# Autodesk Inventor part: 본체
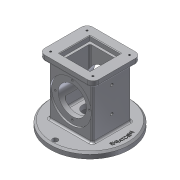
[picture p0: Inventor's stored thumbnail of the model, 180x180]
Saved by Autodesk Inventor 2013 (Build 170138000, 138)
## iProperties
Created: 2019-08
Part Number: 본체
Material: 알루미늄 6061
Document SubType Name: Modeling
Designer: Administrator
Density: 2.71 g/cm^3
Mass: 1042.69 g
Surface Area: 783.577 cm^2
Volume: 384.757 cm^3
Author: Administrator
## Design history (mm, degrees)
sketch "스케치1"
  geometry: L1 (33, 37)-(-33, 37); L2 (-33, 37)-(-33, -37); L3 (-33, -37)-(33, -37); L4 (33, -37)-(33, 37); L5 (33, 37)-(-33, -37); L6 (-33, 37)-(33, -37); 1 further point
  constraints: 12 end point, 2 midpoint, 2 parallel, 1 horizontal, 1 perpendicular
  dimensions: "d0" = 74 distance of L1.end L2.end; "d2" = 66 distance of L1.start L1.end
extrude "돌출1" new body sketch "스케치1" stored distance "d3" = 108; taper "d4" = 0 deg
sketch "스케치2"
  geometry: 2 further points
  constraints: 1 coincident
hole "구멍1" sketch "스케치2" at (54, 37) diameter "d5" = 48; stored, may be unused: countersink angle "d9" = 90 deg, drill point angle "d11" = 118 deg; dims "d6" = 6, "d7" = 70, "d8" = 3, "d10" = 48
sketch "스케치3"
  geometry: C1 r 35 at (0, 0) reference; 1 further point
  constraints: 1 horizontal alignment
  dimensions: "d12" = 29 distance of C1.centre point (-29, 0)
hole "구멍2" sketch "스케치3" at (-29, 0) diameter "d13" = 3.242; stored, may be unused: countersink angle "d17" = 90 deg, drill point angle "d19" = 118 deg; dims "d14" = 4, "d15" = 70, "d16" = 3, "d18" = 6
sketch "스케치4"
  geometry: C1 r 67.5 at (0, 0); 1 further point
  constraints: 1 centre point, 1 coincident
  dimensions: "d23" = 135 diameter of C1
extrude "돌출2" join sketch "스케치4" distance "d25" = 10; taper "d26" = 0 deg
sketch "스케치5"
  geometry: L1 (41, 46)-(-41, 46); L2 (-41, 46)-(-41, -46); L3 (-41, -46)-(41, -46); L4 (41, -46)-(41, 46); L5 (41, 46)-(-41, -46); L6 (-41, 46)-(41, -46); 1 further point
  constraints: 12 end point, 2 midpoint, 2 parallel, 1 horizontal, 1 perpendicular
  dimensions: "d27" = 92 distance between parallel lines of L1 L3; "d29" = 82 distance of L1.start L1.end
extrude "돌출3" join sketch "스케치5" distance "d30" = 10; taper "d31" = 0 deg
fillet "모깎기1" dims "d32" = 10
sketch "스케치6"
  geometry: A1 r 10 centre (-31, 36) between (-31, 46) and (-41, 36) reference; A2 r 10 centre (-31, -36) between (-41, -36) and (-31, -46) reference; A3 r 10 centre (31, -36) between (31, -46) and (41, -36) reference; A4 r 10 centre (31, 36) between (41, 36) and (31, 46) reference; 5 further points
  constraints: 4 coincident
hole "구멍3" sketch "스케치6" at (-31, -36), (31, -36), (-31, 36), (31, 36) diameter "d33" = 3.242; stored, may be unused: countersink angle "d37" = 90 deg, drill point angle "d39" = 118 deg; dims "d34" = 4, "d35" = 70, "d36" = 3, "d38" = 6
sketch "스케치7"
  geometry: L1 (26, 26)-(-26, 26); L2 (-26, 26)-(-26, -26); L3 (-26, -26)-(26, -26); L4 (26, -26)-(26, 26); L5 (26, 26)-(-26, -26); L6 (-26, 26)-(26, -26); 1 further point
  constraints: 12 end point, 2 midpoint, 2 parallel, 2 perpendicular, 1 horizontal
  dimensions: "d40" = 52 distance of L1.end L2.end
extrude "돌출4" cut sketch "스케치7" distance "d42" = 8; taper "d43" = 0 deg
sketch "스케치8"
  geometry: L1 (22, -22)-(-22, -22); L2 (-22, -22)-(-22, 22); L3 (-22, 22)-(22, 22); L4 (22, 22)-(22, -22); L5 (22, -22)-(-22, 22); L6 (-22, -22)-(22, 22); 1 further point
  constraints: 12 end point, 2 midpoint, 2 parallel, 2 perpendicular, 1 horizontal
  dimensions: "d44" = 44 distance of L2.end L3.end
extrude "돌출5" cut sketch "스케치8" distance "d46" = 74; taper "d47" = 0 deg
sketch "스케치10"
  geometry: L1 (-34.5, 10)-(100.5, 10) reference; 3 further points
  constraints: 2 vertical alignment
  dimensions: "d55" = 37 distance from line of point (33, -27) L1; "d56" = 43 distance of point (33, -70) point (33, -27)
fillet "모깎기2" dims "d64" = 3
fillet "모깎기3" dims "d65" = 3
fillet "모깎기4" dims "d66" = 3
chamfer "모따기1" distance "d79" = 3; stored, may be unused: second distance "d80" = 2, angle "d81" = 45 deg
sketch "스케치13"
  geometry: C1 r 64.5 at (0, 0) reference; 3 further points
  constraints: 2 horizontal alignment, 1 vertical alignment
  dimensions: "d82" = 59 distance of point (-59, 0) C1.centre; "d83" = 59 distance of point (0, -59) C1.centre; "d84" = 59 distance of point (59, 0) C1.centre
hole "구멍7" sketch "스케치13" at (-59, 0), (0, -59), (59, 0) diameter "d85" = 9; stored, may be unused: countersink angle "d89" = 90 deg, drill point angle "d91" = 0 deg; dims "d86" = 25, "d87" = 50, "d88" = 18, "d90" = 6
sketch "스케치14"
  geometry: C1 r 4.5 at (-59, 0) reference; C2 r 64.5 at (0, 0) reference; 1 further point
  constraints: 1 coincident, 1 horizontal alignment, 2 other
feature "엠보싱2" sketch "스케치14" dims "d0" = 74, "d2" = 66, "d20" = 40, "d21" = 360 deg, "d92" = 0.5, "d93" = 0
chamfer "모따기2" distance "d94" = 1; stored, may be unused: second distance "d95" = 2, angle "d96" = 45 deg
fillet "모깎기6" dims "d98" = 3
fillet "모깎기7" dims "d99" = 3
sketch "스케치15"
  geometry: C1 r 67.5 at (0, 0) reference; 1 further point
  constraints: 1 coincident
hole "구멍8" sketch "스케치15" at (0, 0) diameter "d100" = 25; stored, may be unused: countersink angle "d104" = 90 deg, drill point angle "d106" = 0 deg; dims "d101" = 25, "d102" = 50, "d103" = 18, "d105" = 6
fillet "모깎기8" dims "d107" = 3
hole "구멍9" sketch "스케치10" diameter "d108" = 4.917; stored, may be unused: countersink angle "d112" = 90 deg, drill point angle "d114" = 0 deg; dims "d109" = 25, "d110" = 50, "d111" = 18, "d113" = 30
node "솔리드1"
pattern_circular "원형 패턴1" dims angle "d21" = 360 deg
mirror "대칭1"
